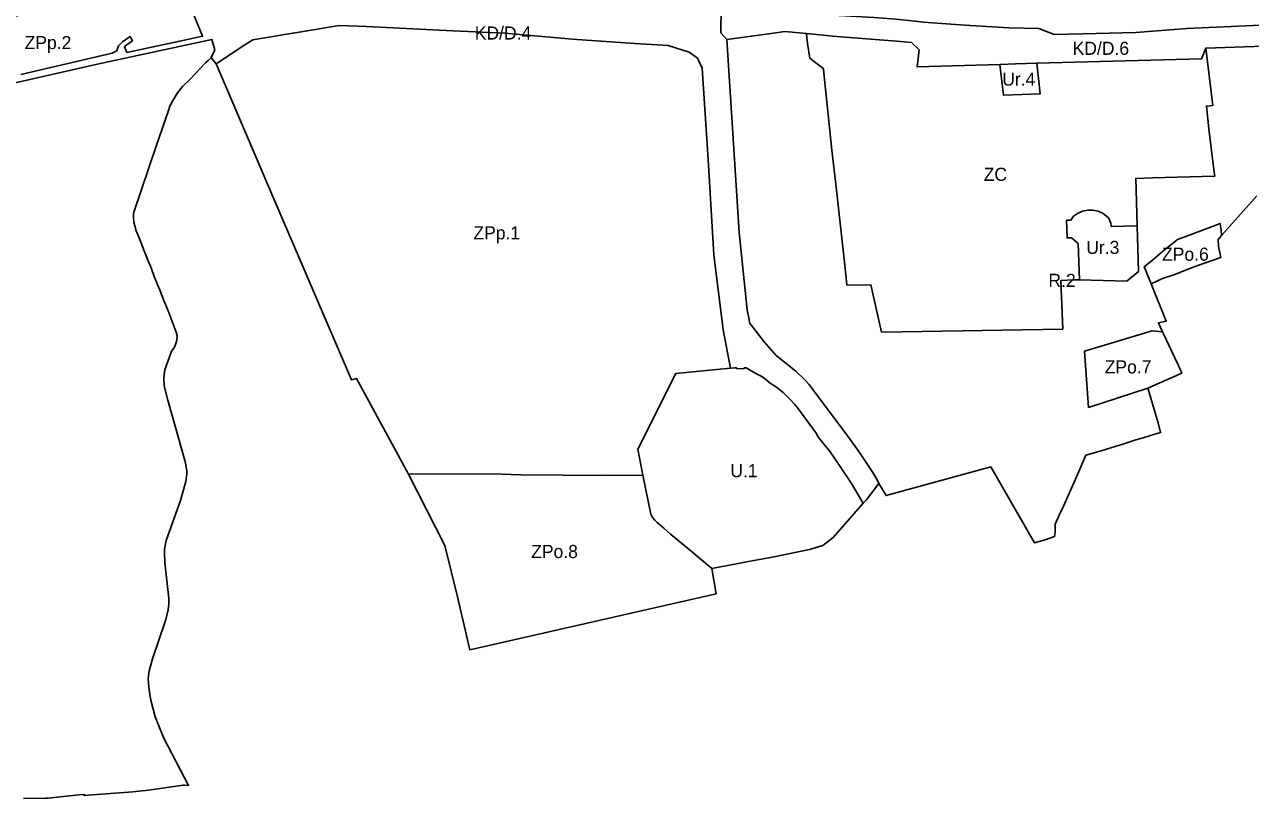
# Model space of a CAD drawing. Extents: x 7418114 to 7422197, y 5546299 to 5548348.
# Drawn here: x 7420780 to 7421715, y 5546334 to 5546924 of the extents above; entities that cross this region are included whole.
import ezdxf

# ---------------------------------------------------------------- set-up
doc = ezdxf.new("R2010")
doc.units = 0
for name, color, linetype in [('_ZWIERZYNIEC_KS_JOZEFA', 7, 'Continuous'), ('linie_rozgraniczajace', 7, 'Continuous'), ('oznaczenia_przeznaczen', 7, 'Continuous')]:
    doc.layers.add(name, color=color, linetype=linetype)

msp = doc.modelspace()

# ---------------------------------------------------------------- linework, layer by layer
at = {"layer": '_ZWIERZYNIEC_KS_JOZEFA'}
msp.add_lwpolyline([(7420713.93, 5546866.43), (7420836.51, 5546894.02), (7420922.7, 5546912.64), (7420924.92, 5546904.72), (7420922.1, 5546898.61), (7420919.97, 5546896.72), (7420917.84, 5546894.89), (7420906.19, 5546882.48), (7420900.38, 5546876.8), (7420896.39, 5546871.92), (7420892.62, 5546865.72), (7420890.69, 5546861.73), (7420889.87, 5546859.25), (7420880.18, 5546831.22), (7420863.17, 5546781.06), (7420862.98, 5546779.76), (7420862.79, 5546776.89), (7420863.15, 5546773.31), (7420864.96, 5546766.84), (7420867.12, 5546761.5), (7420871.13, 5546751.48), (7420875.15, 5546741.46), (7420875.53, 5546740.47), (7420878.53, 5546732.79), (7420881.52, 5546725.1), (7420882.86, 5546721.67), (7420884.2, 5546718.25), (7420886.73, 5546711.94), (7420889.25, 5546705.63), (7420892.41, 5546697.61), (7420895.57, 5546689.58), (7420896.31, 5546686.58), (7420895.91, 5546683.34), (7420895.29, 5546680.71), (7420894.22, 5546677.93), (7420892.03, 5546675.18), (7420891.83, 5546675.05), (7420891.29, 5546673.56), (7420886.89, 5546660.67), (7420886.21, 5546656.93), (7420886.06, 5546654.03), (7420886.34, 5546648.54), (7420889.08, 5546637.53), (7420902.52, 5546589.82), (7420903.54, 5546583.52), (7420903.56, 5546580.82), (7420903.2, 5546577.86), (7420902.85, 5546575.63), (7420900.1, 5546565.67), (7420898.68, 5546561.09), (7420887.82, 5546530.51), (7420886.67, 5546523.93), (7420886.45, 5546520.84), (7420886.9, 5546513.92), (7420889.79, 5546486.29), (7420889.82, 5546482.1), (7420889.42, 5546477.82), (7420887.64, 5546470.24), (7420877.35, 5546440.44), (7420874.88, 5546431.08), (7420874.1, 5546425.25), (7420874.6, 5546418.7), (7420875.76, 5546409.75), (7420879.35, 5546396.19), (7420886.02, 5546379.8), (7420904.95, 5546343.75), (7420902, 5546344), (7420900.85, 5546344.09), (7420874.44, 5546340.22), (7420862.41, 5546338.82), (7420831.47, 5546336.63), (7420825.43, 5546335.98), (7420825.25, 5546336.74), (7420821.26, 5546336.56), (7420797.88, 5546334.18), (7420795.96, 5546334.07), (7420779.04, 5546333.83)], dxfattribs=at)
at = {"layer": 'linie_rozgraniczajace'}
for points in [[(7421553.79, 5546920.97), (7421531.13, 5546921.5), (7421501.59, 5546923.39), (7421490.21, 5546924.11), (7421465.88, 5546926.04), (7421459.32, 5546926.73), (7421444.63, 5546928.26), (7421428.25, 5546929.53), (7421419.1, 5546930.04), (7421387.96, 5546931.78), (7421371, 5546933.14), (7421368.66, 5546933.37), (7421356.1, 5546934.62), (7421343.52, 5546937.64), (7421341.49, 5546938.24), (7421327.31, 5546942.41), (7421315.01, 5546947.03), (7421309.95, 5546950.02), (7421309.16, 5546958.19)], [(7420755.47, 5546926.13), (7420781.14, 5546932.55), (7420800.87, 5546935.66), (7420824.16, 5546937.23), (7420877.16, 5546941.96), (7420905.73, 5546943.27), (7420906, 5546938.81), (7420915.67, 5546915.2), (7420898.14, 5546911.45), (7420877.93, 5546907.06), (7420857.9, 5546902.82), (7420855.94, 5546907.32), (7420862.19, 5546911.74), (7420860.39, 5546914.87), (7420854.39, 5546910.97), (7420851.46, 5546907.91), (7420850.11, 5546903.94), (7420846.65, 5546902.19), (7420776.89, 5546885.89)], [(7420776.89, 5546885.89), (7420846.65, 5546902.19), (7420850.11, 5546903.94), (7420851.46, 5546907.91), (7420854.39, 5546910.97), (7420860.39, 5546914.87), (7420862.19, 5546911.74), (7420855.94, 5546907.32), (7420857.9, 5546902.82), (7420877.93, 5546907.06), (7420898.14, 5546911.45), (7420915.67, 5546915.2), (7420906, 5546938.81)], [(7421311.45, 5546937.53), (7421311.28, 5546917.83), (7421315.82, 5546912.62), (7421325.17, 5546765.45), (7421331.18, 5546706.51), (7421332.77, 5546699.26), (7421333.09, 5546696.48), (7421344.16, 5546682.04), (7421353.16, 5546671.83), (7421368.75, 5546659.59), (7421375.08, 5546653.44), (7421378.57, 5546649.55), (7421384.14, 5546642.01), (7421405.82, 5546613.11), (7421415.14, 5546600.29), (7421419.56, 5546593.8), (7421423.71, 5546587.67), (7421427.13, 5546582.35), (7421430.23, 5546577.32), (7421431.87, 5546573.98), (7421427.06, 5546567.76), (7421422.14, 5546561.32), (7421420.77, 5546559.96), (7421419.93, 5546559), (7421410.42, 5546574.94), (7421401.85, 5546587.69), (7421394.55, 5546598.09), (7421385.64, 5546609.16), (7421383.86, 5546612.57), (7421369.84, 5546631.43), (7421367.3, 5546634.53), (7421364.38, 5546637.88), (7421358.85, 5546643.39), (7421353.78, 5546647.56), (7421348.78, 5546650.58), (7421343.1, 5546655.38), (7421337.98, 5546657.94), (7421330.44, 5546662.34), (7421329.69, 5546662.18), (7421329.05, 5546662.23), (7421328.75, 5546661.54), (7421323.35, 5546661.64), (7421323.22, 5546662.2), (7421321.8, 5546662.25), (7421318.57, 5546661.93), (7421312.95, 5546691.37), (7421305.95, 5546748.39), (7421301.39, 5546821.21), (7421297.03, 5546890.89), (7421293.37, 5546898.48), (7421287.05, 5546902.93), (7421270.91, 5546908.24), (7421245.63, 5546909.55), (7421197.77, 5546912.93), (7421146.23, 5546917.65), (7421106.68, 5546919.38), (7421040.68, 5546922.54), (7421019.92, 5546923.3), (7420953.92, 5546912.45), (7420947.74, 5546908.62), (7420925.96, 5546894.17), (7420922.55, 5546898.28), (7420922.27, 5546898.98)], [(7421762.38, 5546908.91), (7421681.35, 5546906.04), (7421678.15, 5546897.97), (7421552.33, 5546894.56), (7421536.08, 5546894.12), (7421524.04, 5546893.74), (7421461.02, 5546891.75), (7421462.49, 5546904.82), (7421456.78, 5546910.39), (7421445.44, 5546911.41), (7421412.32, 5546913.9), (7421396.73, 5546915.35), (7421386.67, 5546916.28), (7421376.66, 5546917.21), (7421360.13, 5546918.75), (7421349.59, 5546917.15), (7421315.82, 5546912.62), (7421311.28, 5546917.83), (7421311.45, 5546937.53)], [(7421465.88, 5546926.04), (7421490.21, 5546924.11), (7421501.59, 5546923.39), (7421531.13, 5546921.5), (7421553.79, 5546920.97), (7421565.59, 5546916.39), (7421587.51, 5546917), (7421617.87, 5546917.84), (7421627.88, 5546918.11), (7421666.87, 5546920.97), (7421723.02, 5546923.6)], [(7421315.82, 5546912.62), (7421349.59, 5546917.15), (7421360.13, 5546918.75), (7421376.66, 5546917.21), (7421376.85, 5546913.94), (7421377.24, 5546909.57), (7421379.06, 5546898.36), (7421389.3, 5546890.62), (7421389.48, 5546889.77), (7421391.14, 5546874.73), (7421393.29, 5546853.03), (7421395.88, 5546828.18), (7421399.3, 5546800.13), (7421406.02, 5546738.41), (7421407.45, 5546725.23), (7421425.56, 5546725.64), (7421433.9, 5546689.52), (7421572.15, 5546691.88), (7421570.78, 5546729), (7421580.15, 5546729.47), (7421585, 5546729.35), (7421620.97, 5546728.45), (7421629.96, 5546735.83), (7421628.96, 5546770.67), (7421627.92, 5546806.79), (7421640.83, 5546807.18), (7421659.52, 5546807.7), (7421688.13, 5546808.56), (7421687.6, 5546811.58), (7421683.76, 5546844.55), (7421681.75, 5546861.87), (7421686.67, 5546862.26), (7421681.35, 5546906.04), (7421762.38, 5546908.91)], [(7421723.02, 5546923.6), (7421666.87, 5546920.97), (7421627.88, 5546918.11), (7421617.87, 5546917.84), (7421587.51, 5546917), (7421565.59, 5546916.39), (7421553.79, 5546920.97)], [(7420922.27, 5546898.98), (7420924.92, 5546904.72), (7420922.7, 5546912.64), (7420836.51, 5546894.02), (7420713.93, 5546866.43), (7420701.8, 5546864.9), (7420700.53, 5546860.07), (7420699.77, 5546860.32), (7420694.03, 5546861.09), (7420686.03, 5546862.87), (7420677.15, 5546867.56), (7420655.67, 5546880.34)], [(7421415.14, 5546600.29), (7421405.82, 5546613.11), (7421384.14, 5546642.01), (7421378.57, 5546649.55), (7421375.08, 5546653.44), (7421368.75, 5546659.59), (7421353.16, 5546671.83), (7421344.16, 5546682.04), (7421333.09, 5546696.48), (7421332.77, 5546699.26), (7421331.18, 5546706.51), (7421325.17, 5546765.45), (7421315.82, 5546912.62)], [(7421720.39, 5546793.42), (7421693.4, 5546763.27), (7421692.96, 5546767.3), (7421692.39, 5546772.43), (7421668.23, 5546763.26), (7421659.61, 5546760.04), (7421657.08, 5546758.01), (7421648.07, 5546750.67), (7421640.79, 5546744.71), (7421634.19, 5546739.25), (7421636.28, 5546734.53), (7421636.61, 5546733.71), (7421639.62, 5546726.24), (7421651.09, 5546697.75), (7421645.2, 5546696.53), (7421648.4, 5546689.67), (7421640.4, 5546690.39), (7421588.87, 5546675.08), (7421591.86, 5546632.05), (7421637.21, 5546646.8), (7421638.1, 5546643.34), (7421642.8, 5546627.9), (7421645.01, 5546620.37), (7421646.85, 5546612.88), (7421644.96, 5546612.48), (7421631.7, 5546608.42), (7421628.03, 5546607.29), (7421619.43, 5546604.66), (7421601.55, 5546599.06), (7421589.75, 5546595.58), (7421583.79, 5546581.34), (7421579.95, 5546572.77), (7421572.76, 5546556.8), (7421569.74, 5546550.32), (7421566.39, 5546542.93), (7421566.32, 5546536.78), (7421565.92, 5546533.59), (7421558.84, 5546531.18), (7421550.71, 5546528.72), (7421517.24, 5546586.81), (7421437.3, 5546564.85), (7421431.87, 5546573.98), (7421430.23, 5546577.32), (7421427.13, 5546582.35), (7421423.71, 5546587.67), (7421419.56, 5546593.8), (7421415.14, 5546600.29)]]:
    msp.add_lwpolyline(points, dxfattribs=at)
for points in [[(7420925.96, 5546894.17), (7420947.74, 5546908.62), (7420953.92, 5546912.45), (7421019.92, 5546923.3), (7421040.68, 5546922.54), (7421106.68, 5546919.38), (7421146.23, 5546917.65), (7421197.77, 5546912.93), (7421245.63, 5546909.55), (7421270.91, 5546908.24), (7421287.05, 5546902.93), (7421293.37, 5546898.48), (7421297.03, 5546890.89), (7421301.39, 5546821.21), (7421305.95, 5546748.39), (7421312.95, 5546691.37), (7421318.57, 5546661.93), (7421276.76, 5546658.05), (7421247.78, 5546600.27), (7421251.65, 5546580.53), (7421221.95, 5546580.09), (7421190.72, 5546580.43), (7421158.84, 5546580.72), (7421136.06, 5546581.41), (7421072.67, 5546581.16), (7421033.16, 5546654.25), (7421029.18, 5546653.11), (7420966.96, 5546798.33), (7420947.72, 5546843.62)], [(7421376.66, 5546917.21), (7421386.67, 5546916.28), (7421396.73, 5546915.35), (7421412.32, 5546913.9), (7421445.44, 5546911.41), (7421456.78, 5546910.39), (7421462.49, 5546904.82), (7421461.02, 5546891.75), (7421524.04, 5546893.74), (7421526.82, 5546870.32), (7421554.99, 5546871.32), (7421552.33, 5546894.56), (7421678.15, 5546897.97), (7421681.35, 5546906.04), (7421686.67, 5546862.26), (7421681.75, 5546861.87), (7421683.76, 5546844.55), (7421687.6, 5546811.58), (7421688.13, 5546808.56), (7421659.52, 5546807.7), (7421640.83, 5546807.18), (7421627.92, 5546806.79), (7421628.96, 5546770.67), (7421609.2, 5546770.16), (7421608.85, 5546772.64), (7421607.07, 5546776.79), (7421603.1, 5546780.01), (7421599.1, 5546781.67), (7421595.02, 5546782.51), (7421591.34, 5546782.53), (7421587.19, 5546781.82), (7421583.33, 5546780.05), (7421580.46, 5546777.87), (7421578.39, 5546774.95), (7421574.97, 5546774.81), (7421575.52, 5546761.31), (7421578.87, 5546761.45), (7421582.2, 5546758.54), (7421583.95, 5546757), (7421585, 5546729.35), (7421580.15, 5546729.47), (7421570.78, 5546729), (7421572.15, 5546691.88), (7421433.9, 5546689.52), (7421425.56, 5546725.64), (7421407.45, 5546725.23), (7421406.02, 5546738.41), (7421399.3, 5546800.13), (7421395.88, 5546828.18), (7421393.29, 5546853.03), (7421391.14, 5546874.73), (7421389.48, 5546889.77), (7421389.3, 5546890.62), (7421379.06, 5546898.36), (7421377.24, 5546909.57), (7421376.85, 5546913.94)], [(7421524.04, 5546893.74), (7421536.08, 5546894.12), (7421552.33, 5546894.56), (7421554.99, 5546871.32), (7421526.82, 5546870.32)], [(7421575.52, 5546761.31), (7421574.97, 5546774.81), (7421578.39, 5546774.95), (7421580.46, 5546777.87), (7421583.33, 5546780.05), (7421587.19, 5546781.82), (7421591.34, 5546782.53), (7421595.02, 5546782.51), (7421599.1, 5546781.67), (7421603.1, 5546780.01), (7421607.07, 5546776.79), (7421608.85, 5546772.64), (7421609.2, 5546770.16), (7421628.96, 5546770.67), (7421629.96, 5546735.83), (7421620.97, 5546728.45), (7421585, 5546729.35), (7421583.95, 5546757), (7421582.2, 5546758.54), (7421578.87, 5546761.45)], [(7421634.19, 5546739.25), (7421640.79, 5546744.71), (7421648.07, 5546750.67), (7421657.08, 5546758.01), (7421659.61, 5546760.04), (7421668.23, 5546763.26), (7421692.39, 5546772.43), (7421692.96, 5546767.3), (7421693.4, 5546763.27), (7421690.66, 5546760.21), (7421691.02, 5546755.05), (7421691.23, 5546753.84), (7421692.91, 5546746.39), (7421680.27, 5546742.07), (7421674.46, 5546740), (7421672.36, 5546739.25), (7421669.2, 5546738.12), (7421656.9, 5546733.28), (7421648.21, 5546730.34), (7421639.62, 5546726.24), (7421636.61, 5546733.71), (7421636.28, 5546734.53)], [(7421588.87, 5546675.08), (7421640.4, 5546690.39), (7421648.4, 5546689.67), (7421649.61, 5546687.07), (7421654.95, 5546675.64), (7421660.4, 5546663.99), (7421663.12, 5546658.33), (7421654.48, 5546654.49), (7421637.21, 5546646.8), (7421591.86, 5546632.05)], [(7421247.78, 5546600.27), (7421276.76, 5546658.05), (7421318.57, 5546661.93), (7421321.8, 5546662.25), (7421323.22, 5546662.2), (7421323.35, 5546661.64), (7421328.75, 5546661.54), (7421329.05, 5546662.23), (7421329.69, 5546662.18), (7421330.44, 5546662.34), (7421337.98, 5546657.94), (7421343.1, 5546655.38), (7421348.78, 5546650.58), (7421353.78, 5546647.56), (7421358.85, 5546643.39), (7421364.38, 5546637.88), (7421367.3, 5546634.53), (7421369.84, 5546631.43), (7421383.86, 5546612.57), (7421385.64, 5546609.16), (7421394.55, 5546598.09), (7421401.85, 5546587.69), (7421410.42, 5546574.94), (7421419.93, 5546559), (7421404.37, 5546541.34), (7421396.84, 5546532.8), (7421389.06, 5546526.75), (7421378.87, 5546523.81), (7421351.76, 5546518.21), (7421333.45, 5546514.87), (7421304.25, 5546509.3), (7421288.42, 5546522.42), (7421272.6, 5546535.54), (7421267.64, 5546539.88), (7421262.67, 5546544.22), (7421260.81, 5546546.15), (7421258.94, 5546548.08), (7421257.72, 5546550.75), (7421251.65, 5546580.53)], [(7421072.67, 5546581.16), (7421136.06, 5546581.41), (7421158.84, 5546580.72), (7421190.72, 5546580.43), (7421221.95, 5546580.09), (7421251.65, 5546580.53), (7421257.72, 5546550.75), (7421258.94, 5546548.08), (7421260.81, 5546546.15), (7421262.67, 5546544.22), (7421267.64, 5546539.88), (7421272.6, 5546535.54), (7421288.42, 5546522.42), (7421304.25, 5546509.3), (7421307.56, 5546490.01), (7421119.49, 5546447.22), (7421110.3, 5546487.54), (7421100.52, 5546526.64), (7421072.73, 5546581.07)]]:
    msp.add_lwpolyline(points, close=True, dxfattribs=at)

# ---------------------------------------------------------------- texts
at = {"layer": 'oznaczenia_przeznaczen'}
for s, p in [('KD/D.4', (7421123.35, 5546912.65)), ('ZPp.2', (7420779.76, 5546905.35)), ('KD/D.6', (7421579.67, 5546900.97)), ('Ur.4', (7421525.98, 5546877.5)), ('ZC', (7421511.8, 5546804.89)), ('ZPp.1', (7421122.33, 5546760.26)), ('Ur.3', (7421590.1, 5546749.12)), ('ZPo.6', (7421647.92, 5546743.95)), ('R.2', (7421561.2, 5546724)), ('ZPo.7', (7421604.16, 5546658)), ('U.1', (7421318.4, 5546578.84)), ('ZPo.8', (7421166.41, 5546517.2))]:
    msp.add_text(s, height=10, dxfattribs=at).set_placement(p)

doc.saveas('drawing.dxf')
